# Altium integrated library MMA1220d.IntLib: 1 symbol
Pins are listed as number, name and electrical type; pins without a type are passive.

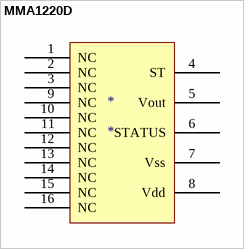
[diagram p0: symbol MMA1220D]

## MMA1220D
designator *
footprint SO-G16/D10.3
pins: 1 NC, 2 NC, 3 NC, 4 ST, 5 Vout, 6 STATUS, 7 Vss, 8 Vdd, 9 NC, 10 NC, 11 NC, 12 NC, 13 NC, 14 NC, 15 NC, 16 NC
